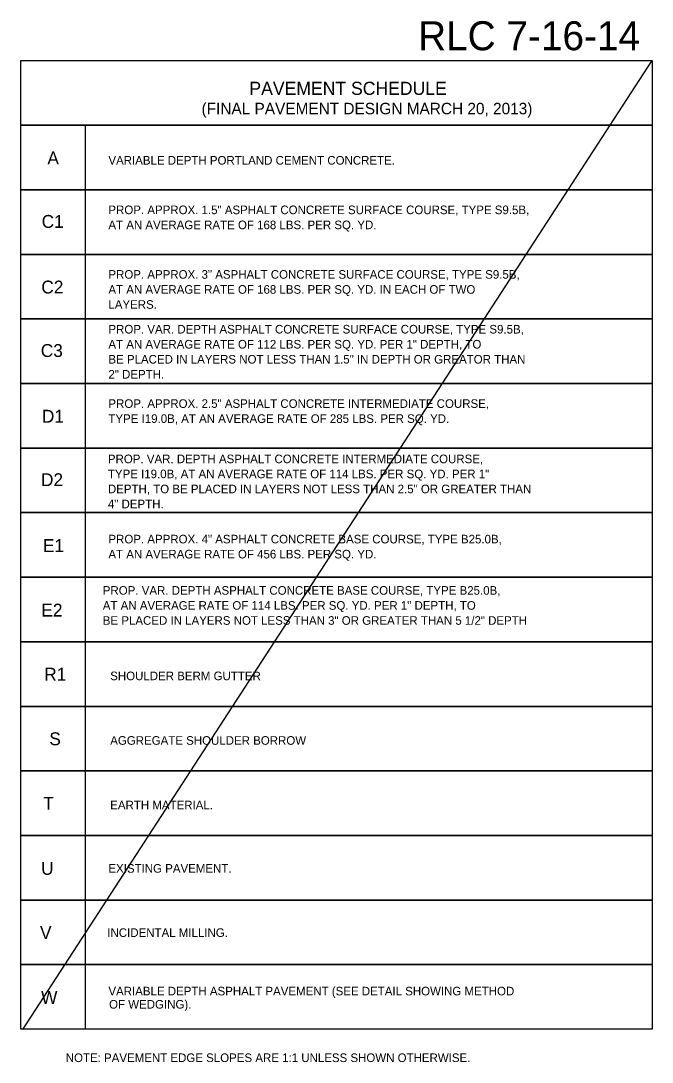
# Model space of a CAD drawing. Extents: x 573732 to 574187, y -53389 to -53257.
# Drawn here: x 574132.2 to 574186.6, y -53364 to -53274.2 of the extents above; entities that cross this region are included whole.
import ezdxf

# ---------------------------------------------------------------- set-up
doc = ezdxf.new("R2010")
doc.units = 0
for name, color, linetype in [('Default', 7, 'Continuous'), ('Old_Level_1', 7, 'Continuous'), ('Old_Level_19', 7, 'Continuous'), ('Old_Level_21', 7, 'Continuous')]:
    doc.layers.add(name, color=color, linetype=linetype)

msp = doc.modelspace()

# ---------------------------------------------------------------- linework, layer by layer
at = {"layer": 'Default'}
msp.add_line((574132.334, -53361.188), (574186.61, -53277.638), dxfattribs=at)
at = {"layer": 'Old_Level_1'}
msp.add_line((574132.334, -53361.188), (574132.334, -53361.188), dxfattribs=at)
at = {"layer": 'Old_Level_19'}
msp.add_lwpolyline([(574132.159, -53277.638), (574186.61, -53277.638), (574186.61, -53283.207), (574132.159, -53283.207)], close=True, dxfattribs=at)
for points in [[(574137.727, -53288.777), (574132.159, -53288.777), (574132.159, -53283.207), (574186.609, -53283.207), (574186.609, -53288.777), (574137.727, -53288.777), (574137.727, -53283.207)], [(574137.727, -53294.345), (574132.159, -53294.345), (574132.159, -53288.775), (574186.609, -53288.775), (574186.609, -53294.345), (574137.727, -53294.345), (574137.727, -53288.775)], [(574137.727, -53299.913), (574132.159, -53299.913), (574132.159, -53294.344), (574186.609, -53294.344), (574186.609, -53299.913), (574137.727, -53299.913), (574137.727, -53294.344)], [(574137.727, -53305.483), (574132.159, -53305.483), (574132.159, -53299.913), (574186.609, -53299.913), (574186.609, -53305.483), (574137.727, -53305.483), (574137.727, -53299.913)], [(574137.727, -53311.052), (574132.159, -53311.052), (574132.159, -53305.483), (574186.609, -53305.483), (574186.609, -53311.052), (574137.727, -53311.052), (574137.727, -53305.483)], [(574137.727, -53316.62), (574132.159, -53316.62), (574132.159, -53311.051), (574186.609, -53311.051), (574186.609, -53316.62), (574137.727, -53316.62), (574137.727, -53311.051)], [(574137.727, -53322.188), (574132.159, -53322.188), (574132.159, -53316.62), (574186.609, -53316.62), (574186.609, -53322.188), (574137.727, -53322.188), (574137.727, -53316.62)], [(574137.727, -53327.757), (574132.159, -53327.757), (574132.159, -53322.188), (574186.609, -53322.188), (574186.609, -53327.757), (574137.727, -53327.757), (574137.727, -53322.188)], [(574137.727, -53333.326), (574132.159, -53333.326), (574132.159, -53327.757), (574186.609, -53327.757), (574186.609, -53333.326), (574137.727, -53333.326), (574137.727, -53327.757)], [(574137.727, -53338.894), (574132.159, -53338.894), (574132.159, -53333.326), (574186.609, -53333.326), (574186.609, -53338.894), (574137.727, -53338.894), (574137.727, -53333.326)], [(574137.727, -53344.463), (574132.159, -53344.463), (574132.159, -53338.894), (574186.609, -53338.894), (574186.609, -53344.463), (574137.727, -53344.463), (574137.727, -53338.894)], [(574137.727, -53350.032), (574132.159, -53350.032), (574132.159, -53344.463), (574186.609, -53344.463), (574186.609, -53350.032), (574137.727, -53350.032), (574137.727, -53344.463)], [(574137.727, -53355.6), (574132.159, -53355.6), (574132.159, -53350.032), (574186.609, -53350.032), (574186.609, -53355.6), (574137.727, -53355.6), (574137.727, -53350.032)], [(574137.727, -53361.169), (574132.159, -53361.169), (574132.159, -53355.6), (574186.609, -53355.6), (574186.609, -53361.169), (574137.727, -53361.169), (574137.727, -53355.6)]]:
    msp.add_lwpolyline(points, dxfattribs=at)

# ---------------------------------------------------------------- texts
at = {"layer": 'Default'}
msp.add_text('RLC 7-16-14', height=2.5, dxfattribs=at).set_placement((574166.422, -53276.741))
at = {"layer": 'Old_Level_21'}
for s, height, p in [('PAVEMENT SCHEDULE', 1.13438, (574151.871, -53280.593)), ('(FINAL PAVEMENT DESIGN MARCH 20, 2013)', 0.9922, (574147.745, -53282.265)), ('A', 1.112, (574134.452, -53286.583)), ('VARIABLE DEPTH PORTLAND CEMENT CONCRETE.', 0.74075, (574139.712, -53286.605)), ('PROP. APPROX. 1.5" ASPHALT CONCRETE SURFACE COURSE, TYPE S9.5B,', 0.74075, (574139.712, -53290.877)), ('C1', 1.1117, (574133.955, -53292.06)), ('AT AN AVERAGE RATE OF 168 LBS. PER SQ. YD. ', 0.74075, (574139.712, -53292.173)), ('PROP. APPROX. 3" ASPHALT CONCRETE SURFACE COURSE, TYPE S9.5B,', 0.74075, (574139.712, -53296.445)), ('C2', 1.1117, (574133.929, -53297.719)), ('AT AN AVERAGE RATE OF 168 LBS. PER SQ. YD. IN EACH OF TWO', 0.74075, (574139.712, -53297.741)), ('LAYERS.', 0.7407, (574139.712, -53299.037)), ('PROP. VAR. DEPTH ASPHALT CONCRETE SURFACE COURSE, TYPE S9.5B,', 0.74075, (574139.712, -53301.17)), ('C3', 1.1117, (574133.882, -53303.195)), ('AT AN AVERAGE RATE OF 112 LBS. PER SQ. YD. PER 1" DEPTH, TO', 0.74075, (574139.712, -53302.465)), ('BE PLACED IN LAYERS NOT LESS THAN 1.5" IN DEPTH OR GREATOR THAN', 0.74075, (574139.712, -53303.761)), ('2" DEPTH.', 0.7407, (574139.712, -53305.057)), ('PROP. APPROX. 2.5" ASPHALT CONCRETE INTERMEDIATE COURSE,', 0.74075, (574139.712, -53307.584)), ('D1', 1.1117, (574133.979, -53308.859)), ('TYPE I19.0B, AT AN AVERAGE RATE OF 285 LBS. PER SQ. YD.', 0.74075, (574139.712, -53308.88)), ('PROP. VAR. DEPTH ASPHALT CONCRETE INTERMEDIATE COURSE,', 0.74075, (574139.668, -53312.354)), ('TYPE I19.0B, AT AN AVERAGE RATE OF 114 LBS. PER SQ. YD. PER 1"', 0.74075, (574139.668, -53313.65)), ('D2', 1.1117, (574133.899, -53314.335)), ('DEPTH, TO BE PLACED IN LAYERS NOT LESS THAN 2.5" OR GREATER THAN', 0.74075, (574139.668, -53314.946)), ('4" DEPTH.', 0.7407, (574139.668, -53316.242)), ('E1', 1.1117, (574134.067, -53320.012)), ('PROP. APPROX. 4" ASPHALT CONCRETE BASE COURSE, TYPE B25.0B,', 0.74075, (574139.712, -53319.272)), ('AT AN AVERAGE RATE OF 456 LBS. PER SQ. YD.', 0.74075, (574139.712, -53320.568)), ('PROP. VAR. DEPTH ASPHALT CONCRETE BASE COURSE, TYPE B25.0B,', 0.74075, (574139.229, -53323.697)), ('E2', 1.1117, (574133.934, -53325.58)), ('AT AN AVERAGE RATE OF 114 LBS. PER SQ. YD. PER 1" DEPTH, TO', 0.74075, (574139.229, -53324.993)), ('BE PLACED IN LAYERS NOT LESS THAN 3" OR GREATER THAN 5 1/2" DEPTH', 0.74075, (574139.229, -53326.289)), ('R1', 1.1117, (574134.179, -53331.108)), ('SHOULDER BERM GUTTER', 0.74075, (574139.868, -53331.068)), ('S', 1.112, (574134.619, -53336.677)), ('AGGREGATE SHOULDER BORROW', 0.74075, (574139.868, -53336.637)), ('T ', 1.1117, (574134.09, -53342.245)), ('EARTH MATERIAL.', 0.74075, (574139.868, -53342.206)), ('U ', 1.1117, (574133.909, -53347.854)), ('EXISTING PAVEMENT.', 0.74075, (574139.712, -53347.671)), ('V ', 1.1117, (574133.813, -53353.392)), ('INCIDENTAL MILLING.', 0.74075, (574139.617, -53353.209)), ('W ', 1.1117, (574133.909, -53358.991)), ('VARIABLE DEPTH ASPHALT PAVEMENT (SEE DETAIL SHOWING METHOD', 0.74074, (574139.712, -53358.252)), ('OF WEDGING).', 0.74074, (574139.772, -53359.389)), ('NOTE: PAVEMENT EDGE SLOPES ARE 1:1 UNLESS SHOWN OTHERWISE.', 0.74075, (574136.034, -53364.001))]:
    msp.add_text(s, height=height, dxfattribs=at).set_placement(p)

doc.saveas('drawing.dxf')
